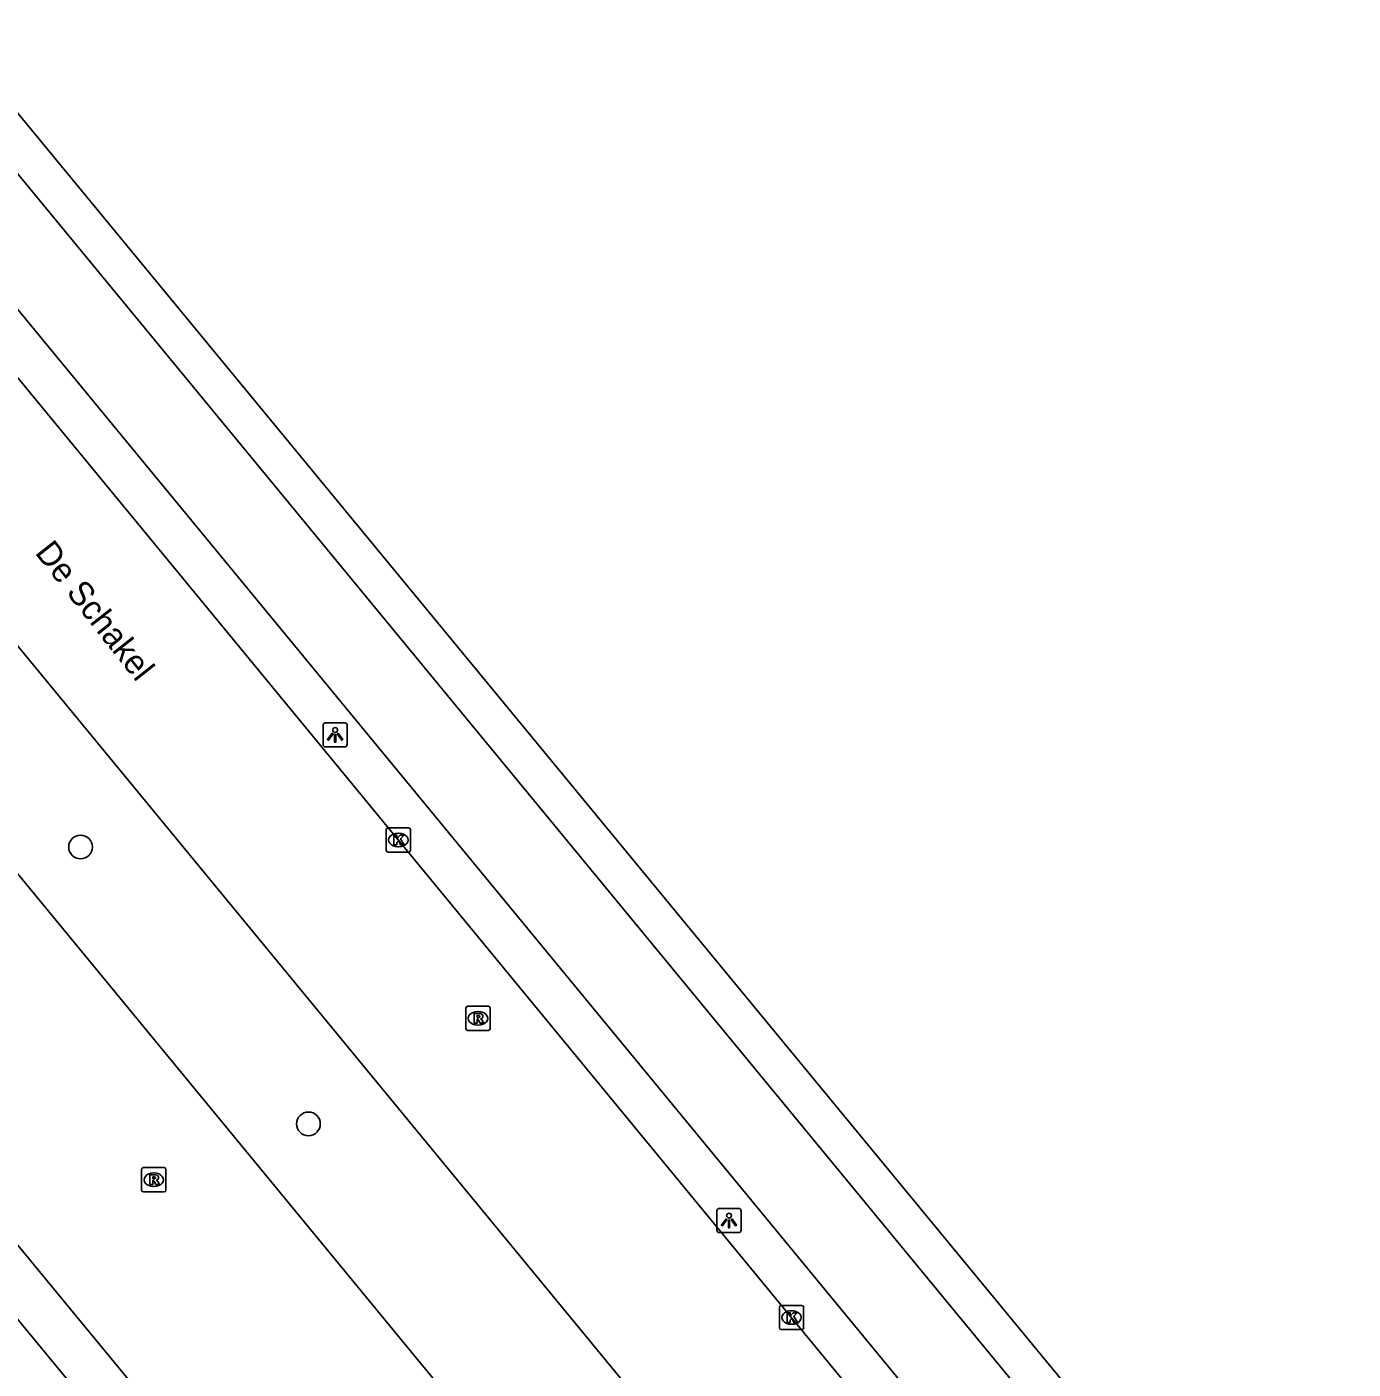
# Model space of a CAD drawing. Extents: x 156141 to 158132, y 385651 to 388399.
# Drawn here: x 157276.3 to 157331.1, y 386292.7 to 386348.1 of the extents above; entities that cross this region are included whole.
import ezdxf

# ---------------------------------------------------------------- set-up
doc = ezdxf.new("R2010")
doc.units = 0
for name, color, linetype in [('IMGEO_Boom', 7, 'Continuous'), ('IMGEO_Fietspad_gesloten', 7, 'Continuous'), ('IMGEO_Kolk', 7, 'Continuous'), ('IMGEO_Lichtpunt', 7, 'Continuous'), ('IMGEO_Openbare_ruimte_label', 7, 'Continuous'), ('IMGEO_Rijbaan_lokaal_gesloten', 7, 'Continuous'), ('IMGEO_Rioolput', 7, 'Continuous'), ('IMGEO_Voetpad_open', 7, 'Continuous')]:
    doc.layers.add(name, color=color, linetype=linetype)

msp = doc.modelspace()

# ---------------------------------------------------------------- linework, layer by layer
at = {"layer": 'IMGEO_Boom'}
for centre in [(157278.547, 386314.257), (157287.953, 386302.83)]:
    msp.add_circle(centre, 0.489, dxfattribs=at)
at = {"layer": 'IMGEO_Fietspad_gesloten'}
for points in [[(157233.279, 386393.841), (157331.128, 386275.064)], [(157230.994, 386391.037), (157326.865, 386274.627)]]:
    msp.add_lwpolyline(points, dxfattribs=at)
at = {"layer": 'IMGEO_Kolk'}
for p, q in [((157291.164, 386314.122), (157291.164, 386314.974)), ((157291.239, 386315.048), (157292.091, 386315.048)), ((157291.652, 386314.828), (157291.677, 386314.828)), ((157292.165, 386314.974), (157292.165, 386314.122)), ((157291.675, 386314.268), (157291.65, 386314.268)), ((157292.091, 386314.048), (157291.239, 386314.048)), ((157307.392, 386294.413), (157307.392, 386295.265)), ((157307.467, 386295.339), (157308.319, 386295.339)), ((157307.88, 386295.119), (157307.905, 386295.119)), ((157308.393, 386295.265), (157308.393, 386294.413)), ((157308.319, 386294.339), (157307.467, 386294.339)), ((157307.903, 386294.559), (157307.878, 386294.559))]:
    msp.add_line(p, q, dxfattribs=at)
for points in [[(157291.164, 386314.122), (157291.164, 386314.974)], [(157291.239, 386315.048), (157292.091, 386315.048)], [(157292.165, 386314.974), (157292.165, 386314.122)], [(157291.485, 386314.748), (157291.608, 386314.748), (157291.608, 386314.597), (157291.738, 386314.748), (157291.902, 386314.748), (157291.756, 386314.597), (157291.909, 386314.348), (157291.757, 386314.348), (157291.672, 386314.512), (157291.608, 386314.445), (157291.608, 386314.348), (157291.485, 386314.348), (157291.485, 386314.748)], [(157292.091, 386314.048), (157291.239, 386314.048)], [(157307.392, 386294.413), (157307.392, 386295.265)], [(157307.467, 386295.339), (157308.319, 386295.339)], [(157307.713, 386295.039), (157307.836, 386295.039), (157307.836, 386294.888), (157307.966, 386295.039), (157308.13, 386295.039), (157307.984, 386294.888), (157308.137, 386294.639), (157307.985, 386294.639), (157307.9, 386294.803), (157307.836, 386294.736), (157307.836, 386294.639), (157307.713, 386294.639), (157307.713, 386295.039)], [(157308.393, 386295.265), (157308.393, 386294.413)], [(157308.319, 386294.339), (157307.467, 386294.339)]]:
    msp.add_lwpolyline(points, dxfattribs=at)
for centre, start, end in [((157291.241, 386314.972), 91.552, 178.448), ((157291.241, 386314.972), 91.552, 178.448), ((157292.089, 386314.972), 1.552, 88.448), ((157292.089, 386314.972), 1.552, 88.448), ((157291.241, 386314.124), 181.552, 268.448), ((157291.241, 386314.124), 181.552, 268.448), ((157292.089, 386314.124), 271.552, 358.448), ((157292.089, 386314.124), 271.552, 358.448), ((157307.469, 386295.263), 91.552, 178.448), ((157307.469, 386295.263), 91.552, 178.448), ((157308.317, 386295.263), 1.552, 88.448), ((157308.317, 386295.263), 1.552, 88.448), ((157307.469, 386294.415), 181.552, 268.448), ((157307.469, 386294.415), 181.552, 268.448), ((157308.317, 386294.415), 271.552, 358.448), ((157308.317, 386294.415), 271.552, 358.448)]:
    msp.add_arc(centre, 0.0765, start, end, dxfattribs=at)
for centre, major_axis, ratio, start_param, end_param in [((157291.651, 386314.548), (-0.387, 0.002), 0.722429, 4.712389, 7.853982), ((157291.676, 386314.548), (-0.39, 0.002), 0.717154, 1.570796, 4.712389), ((157307.879, 386294.839), (-0.387, 0.002), 0.722429, 4.712389, 7.853982), ((157307.904, 386294.839), (-0.39, 0.002), 0.717154, 1.570796, 4.712389)]:
    msp.add_ellipse(centre, major_axis=major_axis, ratio=ratio, start_param=start_param, end_param=end_param, dxfattribs=at)
at = {"layer": 'IMGEO_Lichtpunt'}
for p, q in [((157288.556, 386319.288), (157288.556, 386318.481)), ((157288.556, 386319.288), (157288.556, 386318.481)), ((157289.458, 386319.383), (157288.65, 386319.383)), ((157289.458, 386319.383), (157288.65, 386319.383)), ((157289.552, 386318.481), (157289.552, 386319.288)), ((157289.552, 386318.481), (157289.552, 386319.288)), ((157288.65, 386318.387), (157289.458, 386318.387)), ((157288.65, 386318.387), (157289.458, 386318.387)), ((157305.716, 386299.342), (157304.908, 386299.342)), ((157305.716, 386299.342), (157304.908, 386299.342)), ((157304.814, 386299.247), (157304.814, 386298.44)), ((157304.814, 386299.247), (157304.814, 386298.44)), ((157305.81, 386298.44), (157305.81, 386299.247)), ((157305.81, 386298.44), (157305.81, 386299.247)), ((157304.908, 386298.346), (157305.716, 386298.346)), ((157304.908, 386298.346), (157305.716, 386298.346))]:
    msp.add_line(p, q, dxfattribs=at)
for points in [[(157288.93, 386318.952), (157288.969, 386318.924), (157288.781, 386318.662), (157288.743, 386318.689), (157288.93, 386318.952)], [(157289.032, 386318.904), (157289.079, 386318.904), (157289.079, 386318.582), (157289.032, 386318.582), (157289.032, 386318.904)], [(157289.142, 386318.924), (157289.18, 386318.951), (157289.367, 386318.689), (157289.328, 386318.661), (157289.142, 386318.924)], [(157305.188, 386298.911), (157305.227, 386298.883), (157305.039, 386298.621), (157305.001, 386298.648), (157305.188, 386298.911)], [(157305.29, 386298.863), (157305.337, 386298.863), (157305.337, 386298.541), (157305.29, 386298.541), (157305.29, 386298.863)], [(157305.4, 386298.883), (157305.438, 386298.91), (157305.625, 386298.648), (157305.586, 386298.62), (157305.4, 386298.883)]]:
    msp.add_lwpolyline(points, dxfattribs=at)
for centre in [(157289.055, 386319.086), (157305.313, 386299.045)]:
    msp.add_circle(centre, 0.0994, dxfattribs=at)
for centre, start, end in [((157288.65, 386319.288), 90, 180), ((157288.65, 386319.288), 90, 180), ((157289.458, 386319.288), 0, 90), ((157289.458, 386319.288), 0, 90), ((157288.65, 386318.481), 180, 270), ((157288.65, 386318.481), 180, 270), ((157289.458, 386318.481), 270, 0), ((157289.458, 386318.481), 270, 360), ((157304.908, 386299.247), 90, 180), ((157304.908, 386299.247), 90, 180), ((157305.716, 386299.247), 0, 90), ((157305.716, 386299.247), 0, 90), ((157304.908, 386298.44), 180, 270), ((157304.908, 386298.44), 180, 270), ((157305.716, 386298.44), 270, 0), ((157305.716, 386298.44), 270, 360)]:
    msp.add_arc(centre, 0.0946, start, end, dxfattribs=at)
at = {"layer": 'IMGEO_Rijbaan_lokaal_gesloten'}
for points in [[(157349.183, 386247.253), (157332.608, 386264.801), (157324.262, 386275.047), (157320.799, 386279.156), (157212.168, 386411.116), (157210.786, 386412.789), (157209.596, 386414.647)], [(157203.781, 386410.196), (157205.755, 386407.826), (157335.682, 386250), (157341.401, 386242.711), (157342.288, 386241.546)], [(157337.285, 386238.671), (157336.115, 386240.102), (157327.942, 386250), (157201.153, 386404.033), (157199.193, 386406.39)], [(157265.451, 386312.065), (157270.545, 386304.503), (157271.759, 386302.908), (157316.481, 386248.624)]]:
    msp.add_lwpolyline(points, dxfattribs=at)
at = {"layer": 'IMGEO_Rioolput'}
for p, q in [((157294.453, 386306.759), (157294.453, 386307.611)), ((157294.528, 386307.685), (157295.38, 386307.685)), ((157295.454, 386307.611), (157295.454, 386306.759)), ((157294.941, 386307.465), (157294.966, 386307.465)), ((157295.38, 386306.685), (157294.528, 386306.685)), ((157294.964, 386306.905), (157294.939, 386306.905)), ((157281.07, 386300.098), (157281.07, 386300.95)), ((157281.145, 386301.024), (157281.997, 386301.024)), ((157282.071, 386300.95), (157282.071, 386300.098)), ((157281.558, 386300.804), (157281.583, 386300.804)), ((157281.997, 386300.024), (157281.145, 386300.024)), ((157281.581, 386300.244), (157281.556, 386300.244))]:
    msp.add_line(p, q, dxfattribs=at)
for points in [[(157294.453, 386306.759), (157294.453, 386307.611)], [(157294.528, 386307.685), (157295.38, 386307.685)], [(157295.454, 386307.611), (157295.454, 386306.759)], [(157295.042, 386307.383), (157294.79, 386307.385), (157294.79, 386306.985)], [(157294.79, 386306.985), (157294.914, 386306.985), (157294.914, 386307.147), (157294.925, 386307.147)], [(157294.968, 386307.304), (157294.914, 386307.304), (157294.914, 386307.223)], [(157294.914, 386307.223), (157294.966, 386307.223)], [(157294.972, 386307.118), (157295.043, 386306.985), (157295.183, 386306.985), (157295.118, 386307.111)], [(157295.38, 386306.685), (157294.528, 386306.685)], [(157281.07, 386300.098), (157281.07, 386300.95)], [(157281.145, 386301.024), (157281.997, 386301.024)], [(157282.071, 386300.95), (157282.071, 386300.098)], [(157281.659, 386300.722), (157281.407, 386300.724), (157281.407, 386300.324)], [(157281.407, 386300.324), (157281.531, 386300.324), (157281.531, 386300.486), (157281.542, 386300.486)], [(157281.585, 386300.643), (157281.531, 386300.643), (157281.531, 386300.562)], [(157281.531, 386300.562), (157281.583, 386300.562)], [(157281.589, 386300.457), (157281.66, 386300.324), (157281.8, 386300.324), (157281.735, 386300.45)], [(157281.997, 386300.024), (157281.145, 386300.024)]]:
    msp.add_lwpolyline(points, dxfattribs=at)
for centre, radius, start, end in [((157294.53, 386307.609), 0.0765, 91.552, 178.448), ((157294.53, 386307.609), 0.0765, 91.552, 178.448), ((157295.378, 386307.609), 0.0765, 1.552, 88.448), ((157295.378, 386307.609), 0.0765, 1.552, 88.448), ((157294.924, 386307.094), 0.0533, 26.0293, 88.6989), ((157294.95, 386307.412), 0.19, 274.7715, 282.9687), ((157294.974, 386307.208), 0.0964, 77.0061, 93.1865), ((157294.988, 386307.265), 0.0378, 276.6634, 79.6772), ((157295.041, 386307.273), 0.109, 350.3612, 89.416), ((157295.039, 386307.273), 0.112, 277.5842, 350.9817), ((157295.023, 386307.058), 0.108, 29.5134, 73.7905), ((157294.53, 386306.761), 0.0765, 181.552, 268.448), ((157294.53, 386306.761), 0.0765, 181.552, 268.448), ((157295.378, 386306.761), 0.0765, 271.552, 358.448), ((157295.378, 386306.761), 0.0765, 271.552, 358.448), ((157281.147, 386300.948), 0.0765, 91.552, 178.448), ((157281.147, 386300.948), 0.0765, 91.552, 178.448), ((157281.995, 386300.948), 0.0765, 1.552, 88.448), ((157281.995, 386300.948), 0.0765, 1.552, 88.448), ((157281.541, 386300.433), 0.0533, 26.0293, 88.6989), ((157281.567, 386300.751), 0.19, 274.7715, 282.9687), ((157281.591, 386300.547), 0.0964, 77.0061, 93.1865), ((157281.605, 386300.604), 0.0378, 276.6634, 79.6772), ((157281.658, 386300.612), 0.109, 350.3612, 89.416), ((157281.656, 386300.612), 0.112, 277.5842, 350.9817), ((157281.64, 386300.397), 0.108, 29.5134, 73.7905), ((157281.147, 386300.1), 0.0765, 181.552, 268.448), ((157281.147, 386300.1), 0.0765, 181.552, 268.448), ((157281.995, 386300.1), 0.0765, 271.552, 358.448), ((157281.995, 386300.1), 0.0765, 271.552, 358.448)]:
    msp.add_arc(centre, radius, start, end, dxfattribs=at)
for centre, major_axis, ratio, start_param, end_param in [((157294.94, 386307.185), (-0.387, 0.002), 0.722429, 4.712389, 7.853982), ((157294.965, 386307.185), (-0.39, 0.002), 0.717154, 1.570796, 4.712389), ((157281.557, 386300.524), (-0.387, 0.002), 0.722429, 4.712389, 7.853982), ((157281.582, 386300.524), (-0.39, 0.002), 0.717154, 1.570796, 4.712389)]:
    msp.add_ellipse(centre, major_axis=major_axis, ratio=ratio, start_param=start_param, end_param=end_param, dxfattribs=at)
at = {"layer": 'IMGEO_Voetpad_open'}
for points in [[(157332.344, 386276.123), (157234.228, 386395.166)], [(157250.614, 386325.491), (157310.849, 386252.423), (157319.091, 386238.264)]]:
    msp.add_lwpolyline(points, dxfattribs=at)

# ---------------------------------------------------------------- texts
at = {"layer": 'IMGEO_Openbare_ruimte_label'}
msp.add_text('De Schakel', height=1, rotation=308.302, dxfattribs=at).set_placement((157276.637, 386326.397))

doc.saveas('drawing.dxf')
